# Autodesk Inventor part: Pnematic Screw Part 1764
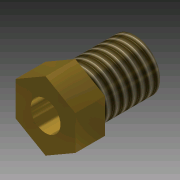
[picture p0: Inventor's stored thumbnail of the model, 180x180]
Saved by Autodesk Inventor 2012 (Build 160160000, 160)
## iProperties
Created: 2010-02
Part Number: Pnematic Screw Part 1764
Document SubType Name: Modeling
Designer: clee1
Density: 1 g/cm^3
Material: Default
Author: clee1
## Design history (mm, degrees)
sketch "Sketch1"
  geometry: C1 r 5.397 at (0, 0); 1 further point
  constraints: 1 centre point, 1 coincident
  dimensions: "d0" = 10.795 diameter of C1
extrude "Extrusion1" new body sketch "Sketch1" distance "d1" = 12.7; taper "d2" = 0 deg
thread "Thread1" dims "d3" = 25.4, "d4" = 0
sketch "Sketch2"
  geometry: L1 (0, 7.332)-(6.35, 3.666); L2 (6.35, 3.666)-(6.35, -3.666); L3 (6.35, -3.666)-(0, -7.332); L4 (0, -7.332)-(-6.35, -3.666); L5 (-6.35, -3.666)-(-6.35, 3.666); L6 (-6.35, 3.666)-(0, 7.332); C1 r 5.397 at (0, 0) reference; 1 further point
  constraints: 12 end point, 13 other
  dimensions: "d5" = 12.7 distance between parallel lines of L2 L5; "d6" = 0 distance of point (0, 0) C1.centre
extrude "Extrusion2" join sketch "Sketch2" distance "d7" = 6.35; taper "d8" = 0 deg
sketch "Sketch5"
  geometry: C1 r 3.175 at (0, 0); 1 further point
  constraints: 1 centre point, 1 coincident
  dimensions: "d14" = 6.35 diameter of C1
extrude "Extrusion5" cut sketch "Sketch5" stored distance "d15" = 25.4; taper "d16" = 0 deg
body "Solid1"
